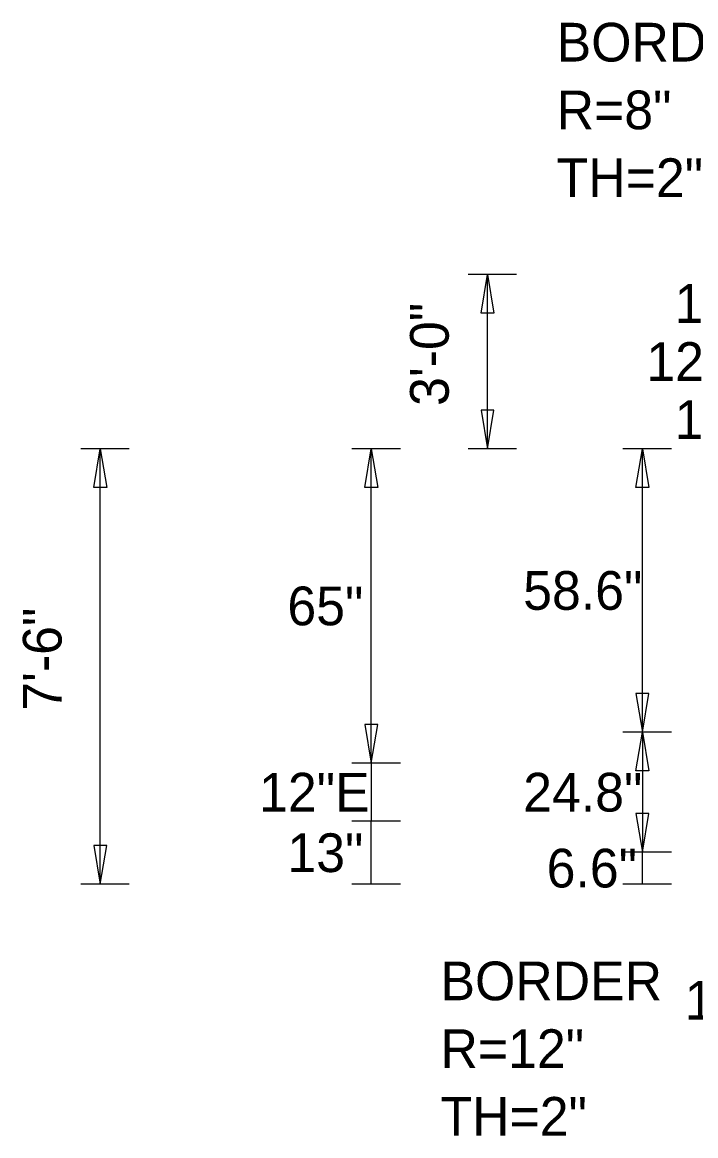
# Model space of a CAD drawing. Extents: x 2149961 to 2150220, y 145114 to 145240.
# Drawn here: x 2149961.42 to 2149973.01, y 145154.09 to 145173.26 of the extents above; entities that cross this region are included whole.
import ezdxf

# ---------------------------------------------------------------- set-up
doc = ezdxf.new("R2010")
doc.units = 0
doc.layers.add('GSDIMS', color=7, linetype='Continuous')

msp = doc.modelspace()

# ---------------------------------------------------------------- linework, layer by layer
at = {"layer": 'GSDIMS'}
for p, q in [((2149969.926, 145168.92), (2149969.093, 145168.92)), ((2149969.426, 145165.919), (2149969.426, 145168.92)), ((2149963.259, 145165.919), (2149962.426, 145165.919)), ((2149962.759, 145158.419), (2149962.759, 145165.919)), ((2149967.926, 145165.919), (2149967.093, 145165.919)), ((2149967.426, 145160.503), (2149967.426, 145165.919)), ((2149969.926, 145165.919), (2149969.093, 145165.919)), ((2149972.593, 145165.919), (2149971.759, 145165.919)), ((2149972.093, 145161.036), (2149972.093, 145165.919)), ((2149972.593, 145161.036), (2149971.759, 145161.036)), ((2149972.593, 145161.036), (2149971.759, 145161.036)), ((2149972.093, 145161.036), (2149972.093, 145158.969)), ((2149967.926, 145160.503), (2149967.093, 145160.503)), ((2149967.926, 145160.503), (2149967.093, 145160.503)), ((2149967.426, 145160.503), (2149967.426, 145159.503)), ((2149967.926, 145159.503), (2149967.093, 145159.503)), ((2149967.926, 145159.503), (2149967.093, 145159.503)), ((2149967.426, 145158.419), (2149967.426, 145159.503)), ((2149972.593, 145158.969), (2149971.759, 145158.969)), ((2149972.593, 145158.969), (2149971.759, 145158.969)), ((2149972.093, 145158.419), (2149972.093, 145158.969)), ((2149963.259, 145158.419), (2149962.426, 145158.419)), ((2149967.926, 145158.419), (2149967.093, 145158.419)), ((2149972.593, 145158.419), (2149971.759, 145158.419))]:
    msp.add_line(p, q, dxfattribs=at)
for points in [[(2149969.426, 145168.92), (2149969.537, 145168.253), (2149969.315, 145168.253)], [(2149969.426, 145165.919), (2149969.537, 145166.585), (2149969.315, 145166.585)], [(2149962.759, 145165.919), (2149962.871, 145165.252), (2149962.648, 145165.252)], [(2149967.426, 145165.919), (2149967.537, 145165.252), (2149967.315, 145165.252)], [(2149972.093, 145165.919), (2149972.204, 145165.252), (2149971.982, 145165.252)], [(2149972.093, 145161.036), (2149972.204, 145161.703), (2149971.982, 145161.703)], [(2149967.426, 145160.503), (2149967.537, 145161.169), (2149967.315, 145161.169)], [(2149972.093, 145161.036), (2149972.204, 145160.369), (2149971.982, 145160.369)], [(2149972.093, 145158.969), (2149972.204, 145159.636), (2149971.982, 145159.636)], [(2149962.759, 145158.419), (2149962.871, 145159.086), (2149962.648, 145159.086)]]:
    msp.add_lwpolyline(points, close=True, dxfattribs=at)

# ---------------------------------------------------------------- texts
for s, p in [('BORDER', (2149970.617, 145172.587)), ('R=8"', (2149970.617, 145171.42)), ('TH=2"', (2149970.617, 145170.253)), ('12"', (2149972.647, 145168.086)), ('12"E', (2149972.161, 145167.086)), ('12"', (2149972.647, 145166.086)), ('58.6"', (2149970.041, 145163.144)), ('65"', (2149965.981, 145162.877)), ('12"E', (2149965.494, 145159.669)), ('24.8"', (2149970.041, 145159.669)), ('13"', (2149965.981, 145158.627)), ('6.6"', (2149970.445, 145158.361)), ('BORDER', (2149968.617, 145156.419)), ('19.05"', (2149972.824, 145156.086)), ('R=12"', (2149968.617, 145155.252)), ('TH=2"', (2149968.617, 145154.086))]:
    msp.add_text(s, height=0.6667, dxfattribs=at).set_placement(p)
for s, p in [('3\'-0"', (2149968.759, 145166.656)), ('7\'-6"', (2149962.093, 145161.405))]:
    msp.add_text(s, height=0.6667, rotation=90, dxfattribs=at).set_placement(p)

doc.saveas('drawing.dxf')
